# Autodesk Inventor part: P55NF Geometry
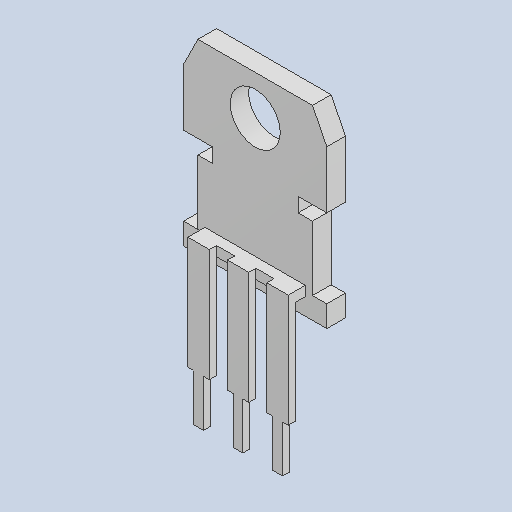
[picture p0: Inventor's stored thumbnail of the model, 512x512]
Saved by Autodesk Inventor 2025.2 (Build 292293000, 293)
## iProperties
Created: 2025-04
Part Number: P55NF Geometry
Material: Generic
Description: PART-P55NF Geometry-DESC
Document SubType Name: Modeling
Designer: BennF
Density: 1 g/cm^3
Appearance: Default
Author: BennF
Revision Number: NONE
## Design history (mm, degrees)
feature "Solid"
body "Solid1"
